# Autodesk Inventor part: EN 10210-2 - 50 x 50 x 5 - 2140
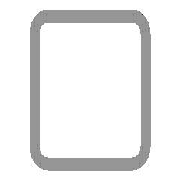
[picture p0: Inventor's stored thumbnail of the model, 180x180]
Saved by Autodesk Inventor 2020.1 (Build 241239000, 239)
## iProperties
_CCFamilyMember: 16
_CCFamilyDisplayName: DIN EN 10210-2 (USAS B17.1 quadratisch) - Rohrleitung — In Klammern angegebene Größen wurden aufgehoben
_FrameMemberDoc: Frame Member File
_Version: 15.0.0
_GetPNFromCC: 1
IsCustomPart: 1
Created: 2019-01
Part Number: EN 10210-2 - 50 x 50 x 5 - 2140
Material: Stahl, weich
Description: Rohrleitung
Document SubType Name: Modeling
Standard: DIN
Designer: lutzd
Standard Revision: 2006-07
Standards Organization: DIN
Language: de-DE
Size Designation: 50 x 50 x 5
Categories: <MemberInstance><Categories><Category DisplayName="Profile" InternalName="089c4875-fa83-4c05-b084-43b9cc11f5ed" Mnemonic="GRDR"><CategoryParameter DisplayName="
Stock Number: 50 x 50 x 5
Mass: 14668.5 g
Surface Area: 7262.22 cm^2
Volume: 1868.59 cm^3
Density: 7.85 g/cm^3
Appearance: Halbpoliert
G_L: 2140,000 mm
G_W: 50,000 mm
G_H: 50,000 mm
DocNumber: ADSK-014216
Folder: .
Dimensions: 50x50x2140 mm
Mass: 14,668 kg
+5DDA6B1B-1EB1-4889-B862-7B623E69D9F4+SCHNITTDETAIL1: Schnittwinkel 90,00 grd
+8EDDD404-C046-467B-8D59-167CF955F028+SCHNITTDETAIL2: Schnittwinkel 90,00 grd
Title: Profil-Bauteil
Author: lutzd
Revision Number: -
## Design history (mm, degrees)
node "Startebene"
node "Endebene"
sketch "Skizze"
  geometry: L1 (-25, -17.5)-(-25, 17.5); L2 (-17.5, 25)-(17.5, 25); L3 (25, 17.5)-(25, -17.5); L4 (17.5, -25)-(-17.5, -25); L5 (-15, 20)-(15, 20); L6 (20, 15)-(20, -15); L7 (15, -20)-(-15, -20); L8 (-20, -15)-(-20, 15); L9 (0, 37.175)-(0, -37.175) reference; L10 (-37.175, 0)-(37.175, 0) reference; A1 r 7.5 centre (-17.5, -17.5) between (-25, -17.5) and (-17.5, -25); A2 r 7.5 centre (-17.5, 17.5) between (-17.5, 25) and (-25, 17.5); A3 r 7.5 centre (17.5, 17.5) between (25, 17.5) and (17.5, 25); A4 r 7.5 centre (17.5, -17.5) between (17.5, -25) and (25, -17.5); A5 r 5 centre (-15, -15) between (-20, -15) and (-15, -20); A6 r 5 centre (-15, 15) between (-15, 20) and (-20, 15); A7 r 5 centre (15, 15) between (20, 15) and (15, 20); A8 r 5 centre (15, -15) between (15, -20) and (20, -15)
  constraints: 16 end point, 16 point on circle, 16 tangent, 8 centre point, 6 equal radius, 4 parallel, 2 perpendicular, 2 other
  dimensions: "d7" = 7.5 radius of A1 (= G_IR); "d10" = 50 distance between parallel lines of L2 L4 (= G_H); "d11" = 50 distance between parallel lines of L1 L3 (= G_W); "d12" = 5 distance between parallel lines of L3 L6 (= G_T); "d15" = 25 distance between parallel lines of L2 L10 (= 0.5 x d10); "d16" = 25 distance between parallel lines of L9 L3 (= 0.5 x d11); "d19" = 5 radius of A5 (= G_T); "d20" = 5 distance between parallel lines of L4 L7 (= G_T)
extrude "Körper" new body sketch "Skizze" stored distance "d3" = 2140 (= G_L); taper "d4" = 0 deg
node "Driven Length"
  sketch "Sketch3"
    geometry: L1 (0, 0)-(10, 0) reference
    constraints: 2 end point, 1 horizontal
  workplane "Work Plane3"
  sketch "Sketch4"
    geometry: L1 (-2, 35)-(12, 35) reference; L2 (-2, 2175)-(12, 2175) reference
    dimensions: "d18" = 2140 distance between parallel lines of L1 L2 (derived)
workplane "Arbeitsebene4"
feature "Trennen1"
workplane "Arbeitsebene5"
feature "Trennen2"
body "Solid1"
other parameters: "G_W" = 50 [user parameter; used in 1 equation term], "G_H" = 50 [user parameter; used in 1 equation term], "G_T" = 5 [user parameter; used in 3 equation terms], "G_IR" = 7.5 [user parameter; used in 1 equation term], "G_L" = 2140 (= d18) [user parameter; used in 1 equation term], "G_OFFSET_START" = -35 [user parameter; used in 1 equation term], "d13" = 35 (= -G_OFFSET_START), "d14" = 2175 (= G_OFFSET_END + B_L), "B_L" = 2225 [user parameter; used in 1 equation term], "d17" = 90 deg
